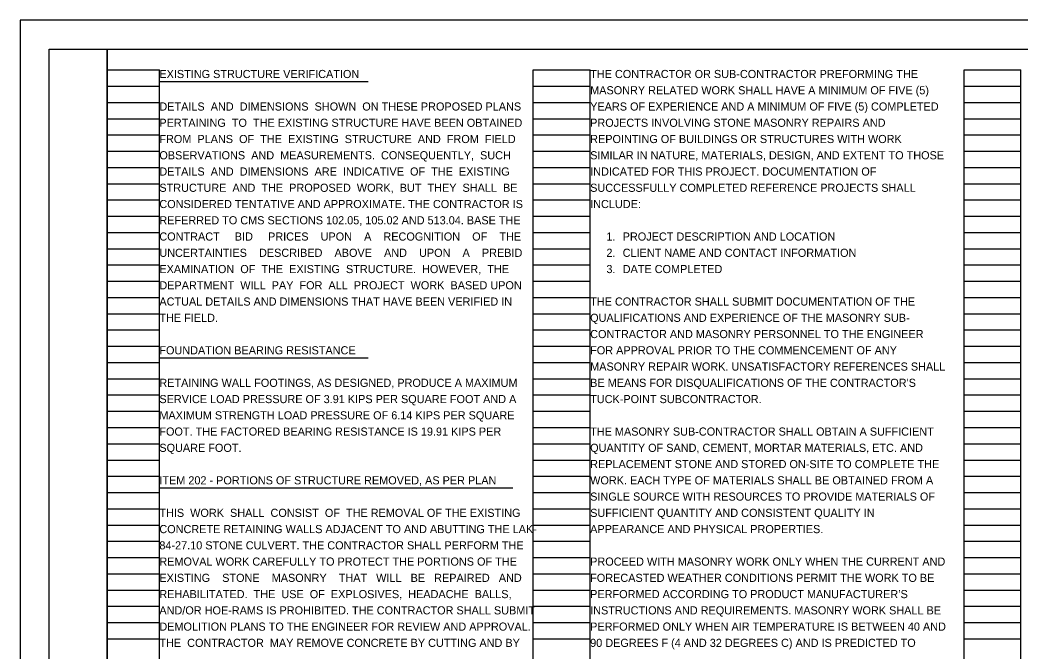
# Model space of a CAD drawing. Extents: x 0 to 63.6, y 0 to 22.
# Drawn here: x 0 to 17.24, y 11.11 to 22 of the extents above; entities that cross this region are included whole.
import ezdxf

# ---------------------------------------------------------------- set-up
doc = ezdxf.new("R2010")
doc.units = 0
for name, color, linetype in [('SH_Border', 7, 'Continuous'), ('SH_Cut_Line', 7, 'Continuous'), ('SH_Data', 7, 'Continuous'), ('SH_Text', 7, 'Continuous')]:
    doc.layers.add(name, color=color, linetype=linetype)

msp = doc.modelspace()

# ---------------------------------------------------------------- linework, layer by layer
at = {"layer": 'SH_Border'}
for points in [[(0.5, 21.5), (1.5, 21.5), (1.5, 0.5), (0.5, 0.5)], [(1.5, 21.5), (33.5, 21.5), (33.5, 0.5), (1.5, 0.5)]]:
    msp.add_lwpolyline(points, close=True, dxfattribs=at)
at = {"layer": 'SH_Cut_Line'}
msp.add_lwpolyline([(0, 0), (34, 0), (34, 22), (0, 22)], close=True, dxfattribs=at)
at = {"layer": 'SH_Data'}
for p, q in [((1.5, 0.98), (1.5, 21.14)), ((1.5, 21.14), (2.4, 21.14)), ((2.4, 0.98), (2.4, 21.14)), ((8.84, 0.98), (8.84, 21.14)), ((8.84, 21.14), (9.82, 21.14)), ((9.82, 0.98), (9.82, 21.14)), ((16.26, 0.98), (16.26, 21.14)), ((16.26, 21.14), (17.24, 21.14)), ((17.24, 0.98), (17.24, 21.14)), ((1.5, 20.86), (2.4, 20.86)), ((8.84, 20.86), (9.82, 20.86)), ((16.26, 20.86), (17.24, 20.86)), ((1.5, 20.58), (2.4, 20.58)), ((8.84, 20.58), (9.82, 20.58)), ((16.26, 20.58), (17.24, 20.58)), ((1.5, 20.3), (2.4, 20.3)), ((8.84, 20.3), (9.82, 20.3)), ((16.26, 20.3), (17.24, 20.3)), ((1.5, 20.02), (2.4, 20.02)), ((8.84, 20.02), (9.82, 20.02)), ((16.26, 20.02), (17.24, 20.02)), ((1.5, 19.74), (2.4, 19.74)), ((8.84, 19.74), (9.82, 19.74)), ((16.26, 19.74), (17.24, 19.74)), ((1.5, 19.46), (2.4, 19.46)), ((8.84, 19.46), (9.82, 19.46)), ((16.26, 19.46), (17.24, 19.46)), ((1.5, 19.18), (2.4, 19.18)), ((8.84, 19.18), (9.82, 19.18)), ((16.26, 19.18), (17.24, 19.18)), ((1.5, 18.9), (2.4, 18.9)), ((8.84, 18.9), (9.82, 18.9)), ((16.26, 18.9), (17.24, 18.9)), ((1.5, 18.62), (2.4, 18.62)), ((8.84, 18.62), (9.82, 18.62)), ((16.26, 18.62), (17.24, 18.62)), ((1.5, 18.34), (2.4, 18.34)), ((8.84, 18.34), (9.82, 18.34)), ((16.26, 18.34), (17.24, 18.34)), ((1.5, 18.06), (2.4, 18.06)), ((8.84, 18.06), (9.82, 18.06)), ((16.26, 18.06), (17.24, 18.06)), ((1.5, 17.78), (2.4, 17.78)), ((8.84, 17.78), (9.82, 17.78)), ((16.26, 17.78), (17.24, 17.78)), ((1.5, 17.5), (2.4, 17.5)), ((8.84, 17.5), (9.82, 17.5)), ((16.26, 17.5), (17.24, 17.5)), ((1.5, 17.22), (2.4, 17.22)), ((8.84, 17.22), (9.82, 17.22)), ((16.26, 17.22), (17.24, 17.22)), ((1.5, 16.94), (2.4, 16.94)), ((8.84, 16.94), (9.82, 16.94)), ((16.26, 16.94), (17.24, 16.94)), ((1.5, 16.66), (2.4, 16.66)), ((8.84, 16.66), (9.82, 16.66)), ((16.26, 16.66), (17.24, 16.66)), ((1.5, 16.38), (2.4, 16.38)), ((8.84, 16.38), (9.82, 16.38)), ((16.26, 16.38), (17.24, 16.38)), ((1.5, 16.1), (2.4, 16.1)), ((8.84, 16.1), (9.82, 16.1)), ((16.26, 16.1), (17.24, 16.1)), ((1.5, 15.82), (2.4, 15.82)), ((8.84, 15.82), (9.82, 15.82)), ((16.26, 15.82), (17.24, 15.82)), ((1.5, 15.54), (2.4, 15.54)), ((8.84, 15.54), (9.82, 15.54)), ((16.26, 15.54), (17.24, 15.54)), ((1.5, 15.26), (2.4, 15.26)), ((8.84, 15.26), (9.82, 15.26)), ((16.26, 15.26), (17.24, 15.26)), ((1.5, 14.98), (2.4, 14.98)), ((8.84, 14.98), (9.82, 14.98)), ((16.26, 14.98), (17.24, 14.98)), ((1.5, 14.7), (2.4, 14.7)), ((8.84, 14.7), (9.82, 14.7)), ((16.26, 14.7), (17.24, 14.7)), ((1.5, 14.42), (2.4, 14.42)), ((8.84, 14.42), (9.82, 14.42)), ((16.26, 14.42), (17.24, 14.42)), ((1.5, 14.14), (2.4, 14.14)), ((8.84, 14.14), (9.82, 14.14)), ((16.26, 14.14), (17.24, 14.14)), ((1.5, 13.86), (2.4, 13.86)), ((8.84, 13.86), (9.82, 13.86)), ((16.26, 13.86), (17.24, 13.86)), ((1.5, 13.58), (2.4, 13.58)), ((8.84, 13.58), (9.82, 13.58)), ((16.26, 13.58), (17.24, 13.58)), ((1.5, 13.3), (2.4, 13.3)), ((8.84, 13.3), (9.82, 13.3)), ((16.26, 13.3), (17.24, 13.3)), ((1.5, 13.02), (2.4, 13.02)), ((8.84, 13.02), (9.82, 13.02)), ((16.26, 13.02), (17.24, 13.02)), ((1.5, 12.74), (2.4, 12.74)), ((8.84, 12.74), (9.82, 12.74)), ((16.26, 12.74), (17.24, 12.74)), ((1.5, 12.46), (2.4, 12.46)), ((8.84, 12.46), (9.82, 12.46)), ((16.26, 12.46), (17.24, 12.46)), ((1.5, 12.18), (2.4, 12.18)), ((8.84, 12.18), (9.82, 12.18)), ((16.26, 12.18), (17.24, 12.18)), ((1.5, 11.9), (2.4, 11.9)), ((8.84, 11.9), (9.82, 11.9)), ((16.26, 11.9), (17.24, 11.9)), ((1.5, 11.62), (2.4, 11.62)), ((8.84, 11.62), (9.82, 11.62)), ((16.26, 11.62), (17.24, 11.62)), ((1.5, 11.34), (2.4, 11.34)), ((8.84, 11.34), (9.82, 11.34)), ((16.26, 11.34), (17.24, 11.34))]:
    msp.add_line(p, q, dxfattribs=at)
at = {"layer": 'SH_Text'}
for p, q in [((2.412, 20.942), (5.998, 20.942)), ((2.412, 16.182), (5.998, 16.182)), ((2.412, 13.942), (8.49, 13.942))]:
    msp.add_line(p, q, dxfattribs=at)

# ---------------------------------------------------------------- texts
for s, p in [('EXISTING STRUCTURE VERIFICATION', (2.4, 21)), ('THE CONTRACTOR OR SUB-CONTRACTOR PREFORMING THE ', (9.82, 21)), ('MASONRY RELATED WORK SHALL HAVE A MINIMUM OF FIVE (5) ', (9.82, 20.72)), ('DETAILS  AND  DIMENSIONS  SHOWN  ON THESE PROPOSED PLANS', (2.4, 20.44)), ('YEARS OF EXPERIENCE AND A MINIMUM OF FIVE (5) COMPLETED ', (9.82, 20.44)), ('PERTAINING  TO  THE EXISTING STRUCTURE HAVE BEEN OBTAINED', (2.4, 20.16)), ('PROJECTS INVOLVING STONE MASONRY REPAIRS AND ', (9.82, 20.16)), ('FROM  PLANS  OF  THE  EXISTING  STRUCTURE  AND  FROM  FIELD', (2.4, 19.88)), ('REPOINTING OF BUILDINGS OR STRUCTURES WITH WORK ', (9.82, 19.88)), ('OBSERVATIONS  AND  MEASUREMENTS.  CONSEQUENTLY,  SUCH', (2.4, 19.6)), ('SIMILAR IN NATURE, MATERIALS, DESIGN, AND EXTENT TO THOSE ', (9.82, 19.6)), ('DETAILS  AND  DIMENSIONS  ARE  INDICATIVE  OF  THE  EXISTING', (2.4, 19.32)), ('INDICATED FOR THIS PROJECT. DOCUMENTATION OF ', (9.82, 19.32)), ('STRUCTURE  AND  THE  PROPOSED  WORK,  BUT  THEY  SHALL  BE', (2.4, 19.04)), ('SUCCESSFULLY COMPLETED REFERENCE PROJECTS SHALL ', (9.82, 19.04)), ('CONSIDERED TENTATIVE AND APPROXIMATE. THE CONTRACTOR IS', (2.4, 18.76)), ('INCLUDE:', (9.82, 18.76)), ('REFERRED TO CMS SECTIONS 102.05, 105.02 AND 513.04. BASE THE', (2.4, 18.48)), ('CONTRACT     BID     PRICES    UPON    A    RECOGNITION    OF    THE', (2.4, 18.2)), ('1.', (10.1, 18.2)), ('PROJECT DESCRIPTION AND LOCATION', (10.38, 18.2)), ('UNCERTAINTIES    DESCRIBED    ABOVE    AND    UPON    A    PREBID', (2.4, 17.92)), ('2.', (10.1, 17.92)), ('CLIENT NAME AND CONTACT INFORMATION', (10.38, 17.92)), ('EXAMINATION  OF  THE  EXISTING  STRUCTURE.  HOWEVER,  THE', (2.4, 17.64)), ('3.', (10.1, 17.64)), ('DATE COMPLETED', (10.38, 17.64)), ('DEPARTMENT  WILL  PAY  FOR  ALL  PROJECT  WORK  BASED UPON', (2.4, 17.36)), ('ACTUAL DETAILS AND DIMENSIONS THAT HAVE BEEN VERIFIED IN', (2.4, 17.08)), ('THE CONTRACTOR SHALL SUBMIT DOCUMENTATION OF THE ', (9.82, 17.08)), ('THE FIELD.', (2.4, 16.8)), ('QUALIFICATIONS AND EXPERIENCE OF THE MASONRY SUB-', (9.82, 16.8)), ('CONTRACTOR AND MASONRY PERSONNEL TO THE ENGINEER ', (9.82, 16.52)), ('FOUNDATION BEARING RESISTANCE', (2.4, 16.24)), ('FOR APPROVAL PRIOR TO THE COMMENCEMENT OF ANY ', (9.82, 16.24)), ('MASONRY REPAIR WORK. UNSATISFACTORY REFERENCES SHALL ', (9.82, 15.96)), ('RETAINING WALL FOOTINGS, AS DESIGNED, PRODUCE A MAXIMUM', (2.4, 15.68)), ("BE MEANS FOR DISQUALIFICATIONS OF THE CONTRACTOR'S ", (9.82, 15.68)), ('SERVICE LOAD PRESSURE OF 3.91 KIPS PER SQUARE FOOT AND A', (2.4, 15.4)), ('TUCK-POINT SUBCONTRACTOR. ', (9.82, 15.4)), ('MAXIMUM STRENGTH LOAD PRESSURE OF 6.14 KIPS PER SQUARE', (2.4, 15.12)), ('FOOT. THE FACTORED BEARING RESISTANCE IS 19.91 KIPS PER', (2.4, 14.84)), ('THE MASONRY SUB-CONTRACTOR SHALL OBTAIN A SUFFICIENT ', (9.82, 14.84)), ('SQUARE FOOT.', (2.4, 14.56)), ('QUANTITY OF SAND, CEMENT, MORTAR MATERIALS, ETC. AND ', (9.82, 14.56)), ('REPLACEMENT STONE AND STORED ON-SITE TO COMPLETE THE ', (9.82, 14.28)), ('ITEM 202 - PORTIONS OF STRUCTURE REMOVED, AS PER PLAN', (2.4, 14)), ('WORK. EACH TYPE OF MATERIALS SHALL BE OBTAINED FROM A ', (9.82, 14)), ('SINGLE SOURCE WITH RESOURCES TO PROVIDE MATERIALS OF ', (9.82, 13.72)), ('THIS  WORK  SHALL  CONSIST  OF  THE REMOVAL OF THE EXISTING', (2.4, 13.44)), ('SUFFICIENT QUANTITY AND CONSISTENT QUALITY IN ', (9.82, 13.44)), ('CONCRETE RETAINING WALLS ADJACENT TO AND ABUTTING THE LAK-', (2.4, 13.16)), ('APPEARANCE AND PHYSICAL PROPERTIES.', (9.82, 13.16)), ('84-27.10 STONE CULVERT. THE CONTRACTOR SHALL PERFORM THE', (2.4, 12.88)), ('REMOVAL WORK CAREFULLY TO PROTECT THE PORTIONS OF THE', (2.4, 12.6)), ('PROCEED WITH MASONRY WORK ONLY WHEN THE CURRENT AND ', (9.82, 12.6)), ('EXISTING    STONE    MASONRY    THAT   WILL   BE   REPAIRED   AND', (2.4, 12.32)), ('FORECASTED WEATHER CONDITIONS PERMIT THE WORK TO BE ', (9.82, 12.32)), ('REHABILITATED.  THE  USE  OF  EXPLOSIVES,  HEADACHE  BALLS,', (2.4, 12.04)), ('PERFORMED ACCORDING TO PRODUCT MANUFACTURER’S ', (9.82, 12.04)), ('AND/OR HOE-RAMS IS PROHIBITED. THE CONTRACTOR SHALL SUBMIT', (2.4, 11.76)), ('INSTRUCTIONS AND REQUIREMENTS. MASONRY WORK SHALL BE ', (9.82, 11.76)), ('DEMOLITION PLANS TO THE ENGINEER FOR REVIEW AND APPROVAL.', (2.4, 11.48)), ('PERFORMED ONLY WHEN AIR TEMPERATURE IS BETWEEN 40 AND ', (9.82, 11.48)), ('THE  CONTRACTOR  MAY REMOVE CONCRETE BY CUTTING AND BY', (2.4, 11.2)), ('90 DEGREES F (4 AND 32 DEGREES C) AND IS PREDICTED TO ', (9.82, 11.2))]:
    msp.add_text(s, height=0.14, rotation=360, dxfattribs=at).set_placement(p)

doc.saveas('drawing.dxf')
